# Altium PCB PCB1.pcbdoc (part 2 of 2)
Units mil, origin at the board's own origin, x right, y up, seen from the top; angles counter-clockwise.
Board outline 4205 x 5050 mil, 2 copper layers (Top Layer, Bottom Layer); 96 components, 86 nets, 386 pads, 487 vias.
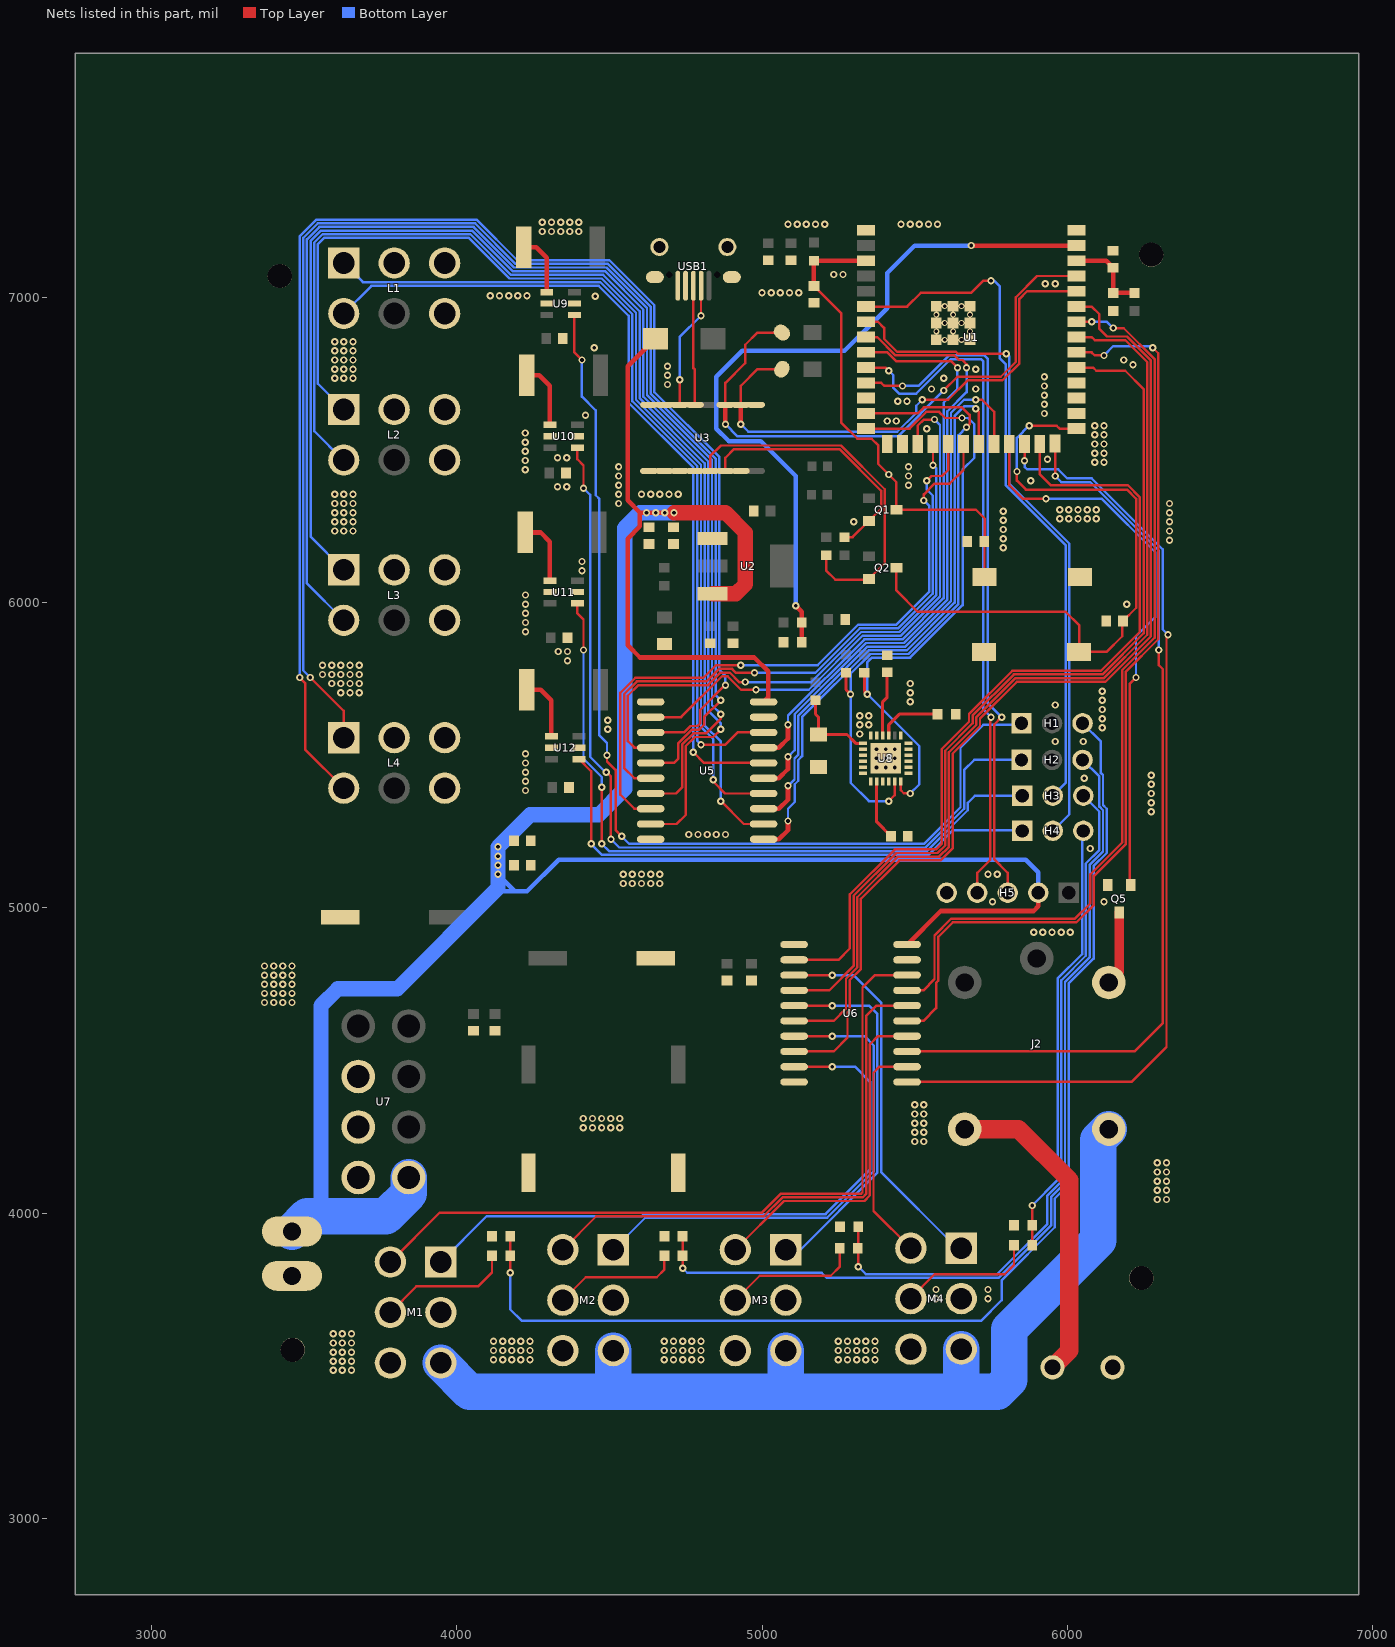
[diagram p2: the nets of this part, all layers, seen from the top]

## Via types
v1: diameter 24.02, hole 12.01, Top Layer to Bottom Layer, 475 vias
v2: diameter 19.69, hole 11.81, Top Layer to Bottom Layer, 12 vias

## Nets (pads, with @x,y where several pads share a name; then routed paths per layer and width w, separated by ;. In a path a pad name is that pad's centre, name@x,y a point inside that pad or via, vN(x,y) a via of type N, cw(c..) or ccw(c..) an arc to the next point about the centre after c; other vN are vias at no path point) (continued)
$1N6809: H3.2 U1.6 | length 2256.7
  Top Layer w8: U1.6@5340.51,6970.19 5475.19,6970.19 5520,7015 5685,7015 5725,7055 v1(5750,7055)
  Bottom Layer w8: v1(5750,7055) 5760,7055 5777.99,7037.01 5777.99,6802.01 5798,6782 5798,6385.03 5994.54,6188.49 5994.54,5409.54 H3.2@5952.5,5367.5
$1N6817: H4.2 U1.7 | length 2195.4
  Top Layer w8: U1.7@5340.51,6920.19 5379.81,6920.19 5400,6900 5400,6864.65 5442.65,6822 5634.97,6822 5641.97,6815 v1(5800,6815)
  Bottom Layer w8: v1(5800,6815) 5801.97,6815 5810,6806.97 5810,6390 6006.54,6193.46 6006.54,5306.54 H4.2@5952.5,5252.5
$2N3281: M1.5 R12.1 | length 441.7
  Top Layer w8: M1.5@3782.33,3675 3867.33,3760 4070,3760 4115.34,3805.34 R12.1@4115.34,3860
$2N3526: M2.5 R14.1 | length 419.2
  Top Layer w8: M2.5@4347.33,3715 4422.33,3790 4655,3790 4680,3815 4680,3859.66 R14.1@4680.34,3860
$2N3663: M3.5 R16.1 | length 449.1
  Top Layer w8: M3.5@4912.33,3715 4992.33,3795 5225,3795 5255,3825 5255,3885.44 R16.1@5254.68,3885.77
$2N3800: M4.5 R18.1 | length 449.7
  Top Layer w8: M4.5@5487.33,3720 5487.33,3722.33 5565,3800 5795,3800 5825.34,3830.34 R18.1@5825.34,3895
$2N3957: J2.4 Q5.3 | length 242.9
  Top Layer w30: J2.4@6136.22,4755.79 6170,4789.57 Q5.3@6170,4984.72
$2N7741: R22.2 U8.9 | length 209.3
  Top Layer w10: U8.9@5414.84,5565.1 5415,5565.26 5415,5600 5449.66,5634.66 R22.2@5575,5634.66
$2N7753: C32.2 U8.10 | length 213.6
  Top Layer w10: U8.10@5395.16,5565.1 5395,5565.26 5395,5675 5410,5690 C32.2@5410,5772.44
$2N7759: C31.2 U8.20 | length 199.4
  Top Layer w10: U8.20@5375.47,5414.9 5375.47,5281.97 C31.2@5422.44,5235
$2N11315: J2.2 P1.1 | length 1048.2
  Top Layer w60: J2.2@5663.81,4275.47 5664.27,4275 5840,4275 6006.55,4108.45 6006.55,3550 P1.1@5951.55,3495
$2N16506: C30.1 R41.1 U8.13 | length 273.2
  Top Layer w10: R41.1@5175,5680.34 5175,5635 5185,5625 C30.1@5185,5568.15 5278.4,5568.15 5307.34,5539.21 U8.13@5329.9,5539.21
+5V: C4.2 C5.2 C28.1 C29.1 D1.1 H5.2 pad.1@3460,3940 U2.3 U5.20 U6.20 U7.4 | length 8374.1
  Top Layer w15: D1.1@4650.51,6865 4560,6774.49 4560,6335 4600,6295 ; v1(4711.58,6295) v1(4681.58,6295) v1(4651.58,6295) v1(4621.58,6295) 4600,6295 ; U5.20@5005.04,5675 5020.04,5690 5020.04,5775 4974.53,5820.51 4600,5820.51 4560,5860.51 4560,6210 4600,6250 4600,6295 ; U6.20@5475.04,4880 5585.04,4990 5890,4990 5905,5005 H5.2@5905,5050
  Top Layer w50: v1(4711.58,6295) 4880,6295 4945,6230 4945,6060.16 4914.29,6029.45 U2.3@4838.07,6029.45
  Bottom Layer w15: 4135,5065 4145,5055 4189.86,5055 ; v1(4135,5109.86) 4189.86,5055 ; H5.2@5905,5050 5905,5116.96 5863.46,5158.5 4333.5,5158.5 4230,5055 4189.86,5055
  Bottom Layer w50: 3555,4040 3555,4680 3610,4735 3805,4735 4135,5065 v1(4135,5109.86) v1(4135,5139.86) v1(4135,5169.86) v1(4135,5200) 4240,5305 4465,5305 4550,5390 4550,6245 4600,6295 v1(4621.58,6295) v1(4651.58,6295) v1(4681.58,6295) v1@4710,6295
  Bottom Layer w120: pad.1@3460,3940 3510,3990 3767.8,3990 3842.68,4064.88 U7.4@3842.68,4116.97
BRAKE: Q5.1 U1.23 | length 1829.9
  Top Layer w8: U1.23@5810,6519.81 5810,6385 5855,6340 v1(5930,6340) ; Q5.1@6207.4,5075.28 6204,5078.68 6204,5734 v1(6225,5755)
  Bottom Layer w8: v1(5930,6340) 6113.03,6340 6288,6165.03 6288,5953 6225,5890 v1(6225,5755)
CHIP_PU: C3.2 C13.2 Q1.3 R2.1 SW1.2 U1.3 | length 1620.3
  Top Layer w8: C3.2@5170,7037.56 5260,6947.56 5260,6589.18 5312.17,6537.01 5359.12,6537.01 5380,6516.12 5380,6455 v1(5415,6420) 5440.28,6394.72 Q1.3@5440.28,6305 5700,6305 5730,6275 5730,6202.44 C13.2@5727.56,6200 5728.66,6198.9 SW1.2@5728.66,6083.65
  Top Layer w15: C3.2@5170,7037.56 R2.1@5170,7120.34 5219.85,7120.34 5220,7120.19 U1.3@5340.51,7120.19
D+: U3.5 USB1.3 | length 392.1
  Top Layer w8: USB1.3@4775,7038.35 4775,6768.35 4780,6763.35 U3.5@4780,6648.35
D-: U3.6 USB1.2 | length 419.2
  Top Layer w8: U3.6@4730,6648.35 v1(4730,6730) ; v1(4800,6940) 4800,7037.86 USB1.2@4800.49,7038.35
  Bottom Layer w8: v1(4730,6730) 4730,6870 v1(4800,6940)
DIR1: U1.25 U6.2 | length 2777.1
  Top Layer w8: U6.2@5104.96,4830 5250,4830 5288,4868 5288,5044.97 5435.03,5192 5570.03,5192 5588,5209.97 5588,5519.97 5678,5609.97 5678,5634.97 5820.03,5777 6110.03,5777 6238,5904.97 6238,6345 6198,6385 5945,6385 5910,6420 U1.25@5910,6519.81
DIR2: U1.31 U6.4 | length 3010.2
  Top Layer w8: U6.4@5104.96,4730 5220,4730 5300,4810 5300,5040 5440,5180 5575,5180 5600,5205 5600,5515 5690,5605 5690,5630 5825,5765 6115,5765 6250,5900 6250,6700 6190,6760 6094.69,6760 6084.49,6770.19 U1.31@6029.49,6770.19
DIR3: U1.33 U6.6 | length 3229
  Top Layer w8: U6.6@5104.96,4630 5235,4630 5275,4670 5275,4768.03 5312,4805.03 5312,5035.03 5444.97,5168 5579.97,5168 5612,5200.03 5612,5510.03 5702,5600.03 5702,5625.03 5829.97,5753 6119.97,5753 6262,5895.03 6262,6788 6190,6860 6089.69,6860 6079.49,6870.19 U1.33@6029.49,6870.19
DIR4: U1.35 U6.8 | length 3418.4
  Top Layer w8: U6.8@5104.96,4530 5235,4530 5280,4575 5280,4658.03 5287,4665.03 5287,4763.06 5324,4800.06 5324,5030.06 5449.94,5156 5584.94,5156 5624,5195.06 5624,5505.06 5714,5595.06 5714,5620.06 5834.94,5741 6124.94,5741 6274,5890.06 6274,6792.97 6194.97,6872 6130,6872 6105,6897 6105,6945 6079.81,6970.19 U1.35@6029.49,6970.19
DTR: Q2.2 R4.1 U3.13 | length 1213.3
  Top Layer w8: U3.13@4830,6431.65 4830,6480 4865,6515 5258.52,6515 5401.91,6371.61 5401.91,6129.78 Q2.2@5349.72,6077.6 5347.13,6075 5240,6075 5210,6105 R4.1@5210,6155.34
ESC1: U1.24 U6.11 | length 3175.7
  Top Layer w8: U6.11@5475.04,4430 6210,4430 6325,4545 6325,5890 v1(6330,5895) ; v1(5860,6465) U1.24@5860,6519.81
  Bottom Layer w8: v1(5860,6465) 5860,6445 5867.99,6437.01 5969.96,6437.01 5999.97,6407 6079.97,6407 6312,6174.97 6312,5913 v1(6330,5895)
ESC2: U1.26 U6.13 | length 2976.3
  Top Layer w8: U6.13@5475.04,4530 6220,4530 6313,4623 6313,5782 6300,5795 v1(6300,5845) ; v1(5960,6415) U1.26@5960,6520.98
  Bottom Layer w8: v1(5960,6415) 5980,6395 6075,6395 6300,6170 v1(6300,5845)
ESC3: U1.32 U6.15 | length 3091
  Top Layer w8: U6.15@5475.04,4630 5528.32,4630 5570,4671.68 5570,4754.71 5577,4761.71 5577,4905.03 5624.97,4953 6029.97,4953 6087,5010.03 6087,5105.03 6192,5210.03 6192,5774.12 6298,5880.12 6298,6817 v1(6280,6835) ; U1.32@6029.49,6820.19 6079.49,6820.19 6089.69,6810 v1(6120,6810)
  Bottom Layer w8: v1(6120,6810) 6150,6840 6275,6840 v1(6280,6835)
ESC4: U1.34 U6.17 | length 2979.5
  Top Layer w8: U6.17@5475.04,4730 5528.32,4730 5565,4766.68 5565,4910 5620,4965 6025,4965 6075,5015 6075,5110 6180,5215 6180,5779.09 6286,5885.09 6286,6797.94 6184.94,6899 6151,6899 v1(6150,6900) ; U1.34@6029.49,6920.19 6029.69,6920 v1(6080,6920)
  Bottom Layer w8: v1(6080,6920) 6130,6920 v1(6150,6900)
FBM1: H1.3 R12.2 R13.1 | length 3959.3
  Top Layer w8: R13.1@4174.66,3925 R12.2@4174.66,3860 4175,3859.66 v1(4175,3805)
  Bottom Layer w8: v1(4175,3805) 4175,3685 4213,3647 5717,3647 5785,3715 5785,3780 5959,3954 5959,4048.09 6004.46,4093.55 6004.46,4752.49 6086,4834.03 6086,5137.06 6129,5180.06 6129,5324.94 6117,5336.94 6117,5434.97 6110,5441.97 6110,5545 H1.3@6050,5605
FBM2: H2.3 R14.2 R15.1 | length 3019.8
  Top Layer w8: R15.1@4739.66,3925 R14.2@4739.66,3860 4740,3859.66 v1(4740,3820)
  Bottom Layer w8: v1(4740,3820) 4755,3805 5195,3805 5212,3788 5774.97,3788 5947,3960.03 5947,4053.06 5992.46,4098.52 5992.46,4757.46 6074,4839 6074,5142.03 6117,5185.03 6117,5319.97 6105,5331.97 6105,5430 H2.3@6050,5485
FBM3: H3.3 R16.2 R17.1 | length 2324.1
  Top Layer w8: R17.1@5314.66,3955 5314.66,3886.43 R16.2@5313.99,3885.77 5315,3884.76 v1(5315,3825)
  Bottom Layer w8: v1(5315,3825) 5340,3800 5770,3800 5935,3965 5935,4058.03 5980.46,4103.49 5980.46,4763.3 6060.46,4843.3 6060.46,5145.46 6105,5190 6105,5315 H3.3@6052.5,5367.5
FBM4: H4.3 R18.2 R19.1 | length 1427
  Top Layer w8: R18.2@5884.66,3895 R19.1@5884.66,3960 5885,3960.34 v1(5885,4025)
  Bottom Layer w8: v1(5885,4025) 5968.46,4108.46 5968.46,4768.27 6048.46,4848.27 6048.46,5248.46 H4.3@6052.5,5252.5
GND: C1.1 C2.1 C3.1 C4.1 C5.1 C6.1 C7.1 C12.2 C13.1 C14.1 C15.2 C20.2 C21.2 C22.2 C23.2 C24.2 C25.2 C26.2 C27.2 C28.2 C29.2 C30.2 C31.1 C32.1 C33.2 C34.2 C35.2 C36.2 C37.2 H5.5 L1.3 L1.6 L2.3 L2.6 L3.3 L3.6 L4.3 L4.6 LED5.1 M1.6 M2.6 M3.6 M4.6 P1.2 pad.1@3460,3795 Q5.2 R9.1 R11.2 R13.2 R15.2 R17.2 R19.2 R22.1 SW1.1 SW2.1 U1.1 U1.40 U1.41 U2.1 U3.1 U5.1 U5.10 U5.19 U6.1 U6.10 U6.19 U7.5 U7.6 U7.7 U8.1 U8.11 U8.18 U8.25 U9.2 U9.5 U10.2 U10.5 U11.2 U11.5 U12.2 U12.5 USB1.5
  other v1: 3595,3485 3625,3485 3655,3485 3595,3515 3625,3515 3655,3515 4120,3520 4150,3520 4180,3520 4210,3520 4240,3520 4680,3520 4710,3520 4740,3520 4770,3520 4800,3520 5250,3520 5280,3520 5310,3520 5340,3520 5370,3520 3595,3545 3625,3545 3655,3545 4120,3550 4150,3550 4180,3550 4210,3550 4240,3550 4680,3550 4710,3550 4740,3550 4770,3550 4800,3550 5250,3550 5280,3550 5310,3550 5340,3550 5370,3550 3595,3575 3625,3575 3655,3575 4120,3580 4150,3580 4180,3580 4210,3580 4240,3580 4680,3580 4710,3580 4740,3580 4770,3580 4800,3580 5250,3580 5280,3580 5310,3580 5340,3580 5370,3580 3595,3605 3625,3605 3655,3605 5570,3720 5740,3720 5570,3750 5740,3750 6295,4045 6325,4045 6295,4075 6325,4075 6295,4105 6325,4105 6295,4135 6325,4135 6295,4165 6325,4165 5500,4235 5530,4235 5500,4265 5530,4265 4414.31,4280.01 4444.31,4280.01 4474.31,4280.01 4504.31,4280.01 4534.31,4280.01 5500,4295 5530,4295 4414.31,4310.01 4444.31,4310.01 4474.31,4310.01 4504.31,4310.01 4534.31,4310.01 5500,4325 5530,4325 5500,4355 5530,4355 3370,4690 3400,4690 3429.45,4690 3460,4690 3370,4720 3400,4720 3429.45,4720 3460,4720 3370,4750 3400,4750 3429.45,4750 3460,4750 3370,4780 3400,4780 3429.45,4780 3460,4780 3370,4810 3400,4810 3429.45,4810 3460,4810 5890,4920 5920,4920 5950,4920 5980,4920 6010,4920 5755,5020 6120,5020 4545,5080 4575,5080 4605,5080 4635,5080 4665,5080 5740,5110 5770,5110 6075,5195 4760,5240.64 4790,5240.64 4820,5240.64 4850,5240.64 4880,5240.64 6275,5315 6275,5345 6275,5375 4225,5385 6275,5405 4225,5415 6055,5425 6275,5435 4225,5445 5375,5460 5405,5460 5435,5460 4225,5475 5375,5490 5405,5490 5435,5490 4225,5505 5375,5520 5405,5520 5435,5520 5960,5545 6052.11,5545 5320,5570 4495,5585 6115,5590 5320,5600 5350,5600 4495,5615 6115,5620 5320,5630 5350,5630 6115,5650 5960,5665 5485,5675 6115,5680 3620,5705 3650,5705 3680,5705 5485,5705 6115,5710 3590,5735 3620,5735 3650,5735 3680,5735 5485,5735 3560,5765 3590,5765 3620,5765 3650,5765 3680,5765 3560,5795 3590,5795 3620,5795 3650,5795 3680,5795 4362.56,5809.95 4332.56,5839.95 4362.56,5839.95 4225,5905 4225,5935 4225,5965 4225,5995 6195,5995 4225,6025 4410,6105 4410,6135 4410,6135 5790,6180 6335,6205 5790,6210 3600,6235 3630,6235 3660,6235 6335,6235 5790,6240 3600,6265 3630,6265 3660,6265 5300,6265 6335,6265 5790,6270 5975,6275 6005,6275 6035,6275 6065,6275 6095,6275 3600,6295 3630,6295 3660,6295 6335,6295 5790,6300 5975,6305 6005,6305 6035,6305 6065,6305 6095,6305 3600,6325 3630,6325 3660,6325 4530,6325 6335,6325 3600,6355 3630,6355 3660,6355 4530,6355 4605,6355 4635,6355 4665,6355 4695,6355 4725,6355 4330,6380 4360,6380 4530,6385 5480,6385 5880,6400 4530,6415 5480,6415 4224.28,6435.84 4530,6445 5480,6445 6090,6460 6120,6460 4224.28,6465.84 5935,6470 4330,6475 4360,6475 6090,6490 6120,6490 4224.28,6495.84 6090,6520 6120,6520 4224.28,6525.84 6090,6550 6120,6550 4224.28,6555.84 5540,6570 6090,6580 6120,6580 5410,6595 5439.29,6595.23 4421.65,6614.19 5925,6620 5925,6650 5445,6660 5475,6660 5925,6680 5555,6700 5700,6700 5925,6710 4690,6715 3600,6735 3630,6735 3660,6735 5595,6735 5925,6740 4690,6745 3600,6765 3630,6765 3660,6765 5700,6765 4690,6775 6215,6780 3600,6795 3630,6795 3660,6795 6185,6795 3600,6825 3630,6825 3660,6825 4450,6835 3600,6855 3630,6855 3660,6855 4453.98,7004.39 4110,7005 4140,7005 4170,7005 4200,7005 4230,7005 5000,7015 5030,7015 5060,7015 5090,7015 5120,7015 5927.47,7045 5960,7045 5235,7075 5265,7075 4280,7215.92 4310,7215.92 4340,7215.92 4370,7215.92 4400,7215.92 5085,7240 5115,7240 5145,7240 5175,7240 5205,7240 5455,7240 5485,7240 5515,7240 5545,7240 5575,7240 4280,7245.92 4310,7245.92 4340,7245.92 4370,7245.92 4400,7245.92
GPIO0: C14.2 Q2.3 SW2.2 U1.27 | length 2201.2
  Top Layer w8: Q2.3@5440.28,6115 5440,6114.72 5440,6040 5510,5970 5995,5970 6038.65,5926.35 SW2.2@6038.65,5838.66 6128.66,5838.66 6180,5890 6180,5937.44 C14.2@6182.56,5940 6226,5983.44 6226,6340.03 6195.51,6370.51 5864.49,6370.51 5835,6400 v1@5835,6420 ; v1(5875,6580) 5875.67,6579.33 5965.35,6579.33 5974.49,6570.19 U1.27@6029.49,6570.19
  Bottom Layer w8: v1(5835,6430) 5835,6540 v1(5875,6580)
H1: U1.17 U5.2 | length 1859.1
  Top Layer w8: U5.2@4634.96,5625 4735,5625 4869,5759 4887.12,5759 4931.12,5715 v1(4980,5715) ; U1.17@5510,6519.81 5510,6580 5530,6600 v1(5565,6600)
  Bottom Layer w8: v1(4980,5715) 5153.03,5715 5330.03,5892 5455.03,5892 5583,6019.97 5583,6582 v1(5565,6600)
H1CS: H1.1 U9.1 | length 3370.1
  Top Layer w8: U9.1@4385.24,6942.6 4385.24,6820 v1(4410,6795.24) v1@4410,6795 ; v1(4492,5500) 4492,5480 4520,5452 4520,5255 v1(4540,5235)
  Bottom Layer w8: v1(4410,6795.24) 4410,6675 4455,6630 4455,6351.97 4467,6339.97 4467,5564.97 4492,5539.97 v1(4492,5500) ; v1(4540,5235) 4565,5210 5530,5210 5650,5330 5650,5525 5725,5600 5845,5600 H1.1@5850,5605
H2: U1.19 U5.6 | length 2047.9
  Top Layer w8: U5.6@4634.96,5425 4581.68,5425 4548,5458.68 4548,5699.97 4590.03,5742 4818.06,5742 4859.06,5783 4902,5783 4915,5770 v1(4975,5770) ; v1(5540,6400) 5555,6415 5590,6415 5610,6435 U1.19@5610,6519.81
  Bottom Layer w8: v1(4975,5770) 5174.09,5770 5320.09,5916 5445.03,5916 5559,6029.97 5559,6351 5540,6370 v1(5540,6400)
H2CS: H2.1 U10.1 | length 2879.3
  Top Layer w8: U10.1@4395.24,6507.6 4395.24,6469.76 4415,6450 v1(4415,6375) ; v1(4490,5445) 4505,5430 v1(4505,5225)
  Bottom Layer w8: v1(4415,6375) 4437.01,6352.99 4437.01,5494.96 4482.66,5449.31 4485.69,5449.31 v1(4490,5445) ; v1(4505,5225) 4532,5198 5534.97,5198 5662,5325.03 5662,5452 5695,5485 H2.1@5850,5485
H3: U1.21 U5.11 | length 1953.5
  Top Layer w8: v1(5700,6635) 5710,6625 U1.21@5710,6519.81
  Top Layer w15: U5.11@5005.04,5225 5055,5225 5085,5255 v1(5085,5285)
  Bottom Layer w8: v1(5085,5285) 5085,5325 5107.01,5347.01 5107.01,5405.04 5118.47,5416.5 5118.47,5484.63 5131.01,5497.17 5131.01,5625.1 5349.91,5844 5474.91,5844 5631,6000.09 5631,6612.06 5662.17,6643.23 5691.77,6643.23 v1(5700,6635)
H3CS: H3.1 U11.1 | length 2297.3
  Top Layer w8: U11.1@4395.24,5997.6 4395.24,5964.76 4415,5945 v1(4415,5845) ; v1(4475,5210) v1(4475,5395)
  Bottom Layer w8: v1(4415,5845) 4415,5488.88 4475,5428.88 v1(4475,5395) ; v1(4475,5210) 4499,5186 5539.94,5186 5674,5320.06 5674,5344 5697.5,5367.5 H3.1@5852.5,5367.5
H4: U1.8 U5.15 | length 2100.5
  Top Layer w8: U1.8@5340.51,6870.19 5377.48,6870.19 5437.68,6810 5630,6810 5645,6795 5656.31,6795 5670,6781.31 v1(5670,6770)
  Top Layer w15: U5.15@5005.04,5425 5055,5425 5085,5455 v1(5085,5495)
  Bottom Layer w8: v1(5085,5495) 5107.01,5517.01 5107.01,5635.04 5339.97,5868 5464.97,5868 5607,6010.03 5607,6627 5670,6690 v1(5670,6770)
H4CS: H4.1 U12.1 | length 1756.1
  Top Layer w8: U12.1@4400.24,5487.6 4440,5447.84 v1(4440,5210)
  Bottom Layer w8: v1(4440,5210) 4476,5174 5544.91,5174 5625.91,5255 5850,5255 H4.1@5852.5,5252.5
HAM1: L1.1 U5.18 | length 2739.6
  Top Layer w8: v1(4800,5535) 4880,5535 4920,5575 U5.18@5005.04,5575
  Bottom Layer w8: L1.1@3629.64,7112.68 3692.33,7050 4470,7050 4575,6945 4575,6660 4788,6447 4788,5547 v1(4800,5535)
HAM2: L2.1 U5.14 | length 3551
  Top Layer w8: v1(4840,5420) 4840,5414.18 4879.18,5375 U5.14@5005.04,5375
  Bottom Layer w8: L2.1@3629.64,6632.68 3545,6717.33 3545,7175 3565,7195 4040,7195 4173,7062 4474.97,7062 4587,6949.97 4587,6664.97 4800,6451.97 4800,5593.03 4840,5553.03 v1(4840,5420)
HAM3: L3.1 U5.9 | length 4304.1
  Top Layer w8: U5.9@4634.96,5275 4720,5275 4750,5305 4750,5530 4780,5560 4840,5560 v1(4865,5585)
  Bottom Layer w8: L3.1@3629.64,6107.68 3521,6216.33 3521,7184.94 3555.06,7219 4049.94,7219 4182.94,7086 4484.91,7086 4611,6959.91 4611,6674.91 4824,6461.91 4824,5644.88 4865,5603.88 v1(4865,5585)
HAM4: L4.1 U5.5 | length 4707.2
  Top Layer w8: v1(3520,5755) 3629.65,5645.35 L4.1@3629.64,5557.68 ; U5.5@4634.96,5475 4711,5475 4726,5490 4726,5539.94 4770.06,5584 4794,5584 4810,5600 4810,5625 v1(4865,5680)
  Bottom Layer w8: v1(3520,5755) 3497,5778 3497,7194.88 3545.12,7243 4059.88,7243 4192.88,7110 4494.85,7110 4635,6969.85 4635,6684.85 4848,6471.85 4848,5697 v1(4865,5680)
IN-1: L1.2 R37.1 U9.4 | length 202.7
  Top Layer w15: R37.1@4219.28,7165 4260,7165 4294.76,7130.24 U9.4@4294.76,7017.4
IN-2: L2.2 R38.1 U10.4 | length 217.7
  Top Layer w15: R38.1@4229.28,6745 4270,6745 4304.76,6710.24 U10.4@4304.76,6582.4
IN-3: L3.2 R39.1 U11.4 | length 220.7
  Top Layer w15: R39.1@4224.28,6230 4275,6230 4304.76,6200.24 U11.4@4304.76,6072.4
IN-4: L4.2 R40.1 U12.4 | length 212.7
  Top Layer w15: R40.1@4229.28,5715 4275,5715 4309.76,5680.24 U12.4@4309.76,5562.4
M+: J2.3 M1.3 M2.3 M3.3 M4.3 | length 3288.9
  Bottom Layer w120: M1.3@3947.67,3509.65 4042.32,3415 4507.7,3415 ; M2.3@4512.67,3549.65 4512.67,3419.97 4507.7,3415 ; M3.3@5077.67,3549.65 5077.67,3416.45 5076.22,3415 ; M4.3@5652.67,3554.65 5652.67,3423.73 5643.94,3415 ; J2.3@6136.2,4275.47 6101.2,4240.47 6101.2,3911.2 5810,3620 5810,3455 5770,3415 5643.94,3415 ; 4507.7,3415 5076.22,3415 ; 5076.22,3415 5643.94,3415
MDIR1: M1.4 U6.18 | length 2475
  Top Layer w8: M1.4@3782.33,3840.35 3943.98,4002 5000.04,4002 5062.04,4064 5325.06,4064 5329,4067.94 5329,4739 5370,4780 U6.18@5475.04,4780
MDIR2: M2.4 U6.16 | length 1800.5
  Top Layer w8: M2.4@4347.33,3880.35 4456.98,3990 5005.01,3990 5067.01,4052 5330.03,4052 5341,4062.97 5341,4646 5375,4680 U6.16@5475.04,4680
MDIR3: M3.4 U6.14 | length 1142.5
  Top Layer w8: M3.4@4912.33,3880.35 5071.98,4040 5335,4040 5353,4058 5353,4553 5380,4580 U6.14@5475.04,4580
MDIR4: M4.4 U6.12 | length 743.6
  Top Layer w8: U6.12@5475.04,4480 5385,4480 5365,4460 5365,4007.68 M4.4@5487.33,3885.35
MESC1: M1.1 U6.9 | length 2088.5
  Top Layer w8: U6.9@5104.96,4480 v1(5230,4480)
  Bottom Layer w8: M1.1@3947.67,3840.35 4097.33,3990 4605.36,3990 4612.36,3997 5208.06,3997 5354,4142.94 5354,4430 5304,4480 v1(5230,4480)
MESC2: M2.1 U6.7 | length 1644.9
  Top Layer w8: U6.7@5104.96,4580 v1(5230,4580)
  Bottom Layer w8: M2.1@4512.67,3880.35 4617.33,3985 5213.03,3985 5366,4137.97 5366,4549 5335,4580 v1(5230,4580)
MESC3: M3.1 U6.5 | length 1208.6
  Top Layer w8: U6.5@5104.96,4680 v1(5230,4680)
  Bottom Layer w8: M3.1@5077.67,3880.35 5125.35,3880.35 5378,4133 5378,4652 5350,4680 v1(5230,4680)
MESC4: M4.1 U6.3 | length 1243.4
  Top Layer w8: U6.3@5104.96,4780 v1(5230,4780)
  Bottom Layer w8: v1(5230,4780) 5300,4780 5390,4690 5390,4135 5639.65,3885.35 M4.1@5652.67,3885.35
RTS: Q1.2 R5.1 U3.14 | length 838.7
  Top Layer w8: U3.14@4880,6431.65 4880,6475 4908,6503 5253.55,6503 5389.91,6366.64 5389.91,6307.78 Q1.2@5349.72,6267.6 5296.79,6214.66 R5.1@5270,6214.66
RXD0: LED4.2 U1.36 U3.2 | length 1720.5
  Top Layer w8: U3.2@4930,6648.35 4930,6710 4985,6765 LED4.2@5065,6765 ; v1(5525,6665) 5610,6665 5673,6728 5786.97,6728 5843,6784.03 5843,6995.22 5867.97,7020.19 U1.36@6029.49,7020.19
  Top Layer w15: v1(4930,6585) U3.2@4930,6648.35
  Bottom Layer w8: v1(4930,6585) 4955,6560 5443.03,6560 5505,6621.97 5505,6645 v1(5525,6665)
RXD1: H5.3 U1.11 | length 2246.3
  Top Layer w8: U1.11@5340.51,6720.19 5390.51,6720.19 5400.7,6710 v1(5460,6710) ; v1(5785,5625) 5760,5600 5760,5160 5805,5115 H5.3@5805,5050
  Bottom Layer w8: v1(5460,6710) 5513.03,6710 5613.03,6810 5729,6810 5739,6800 5739,5671 v1(5785,5625)
S1: U1.18 U5.4 | length 1905
  Top Layer w8: U5.4@4634.96,5525 4581.68,5525 4560,5546.68 4560,5695 4595,5730 4823.03,5730 4864.03,5771 4894,5771 4925,5740 v1(4945,5740) ; v1(5560,6450) U1.18@5560,6519.81
  Bottom Layer w8: v1(4945,5740) 5161.06,5740 5325.06,5904 5450,5904 5571,6025 5571,6439 v1(5560,6450)
S2: U1.20 U5.8 | length 2174.9
  Top Layer w8: U5.8@4634.96,5325 4581.68,5325 4536,5370.68 4536,5704.94 4585.06,5754 4808.09,5754 4849.09,5795 v1(4930,5795) ; v1(5530,6335) 5530,6355 5565,6390 5615,6390 5660,6435 U1.20@5660,6519.81
  Bottom Layer w8: v1(4930,5795) 5182.12,5795 5315.12,5928 5440.06,5928 5547,6034.94 5547,6318 v1(5530,6335)
S3: U1.22 U5.13 | length 1934.8
  Top Layer w8: v1(5700,6665) 5720.63,6665 5760,6625.63 U1.22@5760,6519.81
  Top Layer w15: U5.13@5005.04,5325 5055,5325 5085,5355 v1(5085,5400)
  Bottom Layer w8: v1(5085,5400) 5106.29,5421.29 5106.29,5489.42 5119.01,5502.14 5119.01,5630.07 5344.94,5856 5469.94,5856 5619,6005.06 5619,6622.03 5661.97,6665 v1(5700,6665)
S4: U1.9 U5.17 | length 1930.8
  Top Layer w8: U1.9@5340.51,6820.19 5410.51,6820.19 5439.29,6791.41 5618.59,6791.41 v1(5640,6770)
  Top Layer w15: U5.17@5005.04,5525 5055,5525 5085,5555 v1(5085,5600)
  Bottom Layer w8: v1(5085,5600) 5085,5630 5335,5880 5460,5880 5595,6015 5595,6655 5640,6700 v1(5640,6770)
SCL0: R20.1 U1.13 U8.23 | length 2097.2
  Top Layer w8: U1.13@5340.51,6620.19 5510.19,6620.19 5530,6640 5655,6640 5680,6615 5680,6585 v1(5670,6575) ; v1(5415,5350) 5434.53,5369.53 U8.23@5434.53,5414.9
  Top Layer w10: R20.1@5275,5770.34 5275,5715 v1(5290,5700)
  Bottom Layer w8: v1(5415,5350) 5350,5350 5290,5410 v1(5290,5700) 5290,5767.12 5354.88,5832 5479.88,5832 5643,5995.12 5643,6548 v1(5670,6575)
SDA0: R21.1 U1.14 U8.24 | length 2043.7
  Top Layer w8: U1.14@5340.51,6570.19 5483.22,6570.19 5538.03,6625 5580,6625 5600,6605 v1(5655,6605) ; U8.24@5454.21,5414.9 5454.21,5385.79 5464.21,5375.79 5484.21,5375.79 v1(5485,5375)
  Top Layer w10: R21.1@5335,5770.34 5335,5710 v1(5345,5700)
  Bottom Layer w8: v1(5485,5375) 5515,5405 5515,5530 v1(5345,5700) 5345,5805.15 5359.85,5820 5484.85,5820 5657,5992.15 5657,6435.99 5695,6473.99 5695,6585 5675,6605 v1(5655,6605)
SH1: L1.4 U5.16 | length 2773.9
  Top Layer w8: v1(4775,5510) 4810,5475 U5.16@5005.04,5475
  Bottom Layer w8: L1.4@3629.64,6947.33 3720.32,7038 4465.03,7038 4563,6940.03 4563,6655.03 4775,6443.03 v1(4775,5510)
SH2: L2.4 U5.12 | length 3821.7
  Top Layer w8: v1(4865,5350) 4940,5275 U5.12@5005.04,5275
  Bottom Layer w8: L2.4@3629.64,6467.33 3627.67,6467.33 3533,6562 3533,7179.97 3560.03,7207 4044.97,7207 4177.97,7074 4479.94,7074 4599,6954.94 4599,6669.94 4812,6456.94 4812,5598 4865,5545 v1(4865,5350)
SH3: L3.4 U5.7 | length 4396.8
  Top Layer w8: U5.7@4634.96,5375 4718,5375 4738,5395 4738,5534.97 4775.03,5572 4815.88,5572 4865,5621.12 v1(4865,5635)
  Bottom Layer w8: L3.4@3629.64,5942.33 3509,6062.98 3509,7189.91 3550.09,7231 4054.91,7231 4187.91,7098 4489.88,7098 4623,6964.88 4623,6679.88 4836,6466.88 4836,5664 v1(4865,5635)
SH4: L4.4 U5.3 | length 4844.9
  Top Layer w8: v1(3485,5755) 3503,5737 3503,5518.98 L4.4@3629.64,5392.33 ; U5.3@4634.96,5575 4744.09,5575 4765.09,5596 4789.03,5596 4798,5604.97 4798,5649.31 4878.69,5730 v1(4880,5730)
  Bottom Layer w8: v1(3485,5755) 3485,7199.85 3540.15,7255 4064.85,7255 4197.85,7122 4499.82,7122 4647,6974.82 4647,6689.82 4860,6476.82 4860,5780 4880,5760 v1(4880,5730)
TEMP: R8.1 R9.2 U1.39 | length 2472.4
  Top Layer w15: v1(5110,5990) 5129.66,5970.34 R8.1@5129.66,5935 R9.2@5129.66,5870 ; v1(5685,7170) 6029.3,7170 U1.39@6029.49,7170.19
  Bottom Layer w15: v1(5110,5990) 5110,6415 4995.5,6529.5 4890.5,6529.5 4850,6570 4850,6740 4935,6825 5270,6825 5410,6965 5410,7080 5500,7170 v1(5685,7170)
TXD0: LED3.2 U1.37 U3.3 | length 1930.8
  Top Layer w8: U3.3@4880,6648.35 4880,6720 4945,6785 4945,6845 4985,6885 LED3.2@5065,6885 ; v1(5595,6695) 5640,6740 5782,6740 5831,6789 5831,7000.19 5901,7070.19 U1.37@6029.49,7070.19
  Top Layer w15: v1(4880,6585) U3.3@4880,6648.35
  Bottom Layer w8: v1(4880,6585) 4920,6545 5445,6545 v1(5595,6695)
TXD1: H5.4 U1.10 | length 2263
  Top Layer w8: U1.10@5340.51,6770.19 5404.81,6770.19 v1(5415,6760) ; H5.4@5705,5050 5705,5115 5748,5158 5748,5623 v1(5750,5625)
  Bottom Layer w8: v1(5415,6760) 5430,6745 5430,6703.88 5448.88,6685 5505,6685 5618,6798 5717,6798 5725,6790 5725,5650 v1(5750,5625)
VBATT: C15.1 R10.2 R11.1 U1.38 | length 282.7
  Top Layer w15: U1.38@6029.49,7120.19 6127.24,7120.19 C15.1@6150,7097.44 R11.1@6150,7014.66 R10.2@6220,7014.66
"": M1.2 M2.2 M3.2 M4.2 SCREW3.1 SCREW4.1 U1.12 U1.15 U1.16 U1.28 U1.29 U1.30 U3.7 U3.8 U3.9 U3.10 U3.11 U3.12 U3.15 U8.2 U8.3 U8.4 U8.5 U8.6 U8.7 U8.12 U8.14 U8.15 U8.16 U8.17 U8.19 U8.21 U8.22 USB1.0 USB1.4 USB1.6 USB1.7 USB1.8 USB1.9 USB1.10
  other v1: 4545,5110 4575,5110 4605,5110 4635,5110 4665,5110
  other v2: 5598.38,6861.14 5653.5,6861.14 5570.82,6888.7 5625.94,6888.7 5681.06,6888.7 5598.38,6916.26 5653.5,6916.26 5570.82,6943.81 5625.94,6943.81 5681.06,6943.81 5598.38,6971.37 5653.5,6971.37

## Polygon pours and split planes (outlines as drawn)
GND on Bottom Layer (solid, remove dead copper, pour order 0): 3000,3000 6705,3000 6705,7550 3000,7550
12.6VDC on Top Layer (solid, remove dead copper, pour order 1): 4845,4800 5005,4800 5005,4965 4845,4965
7.4VDC on Top Layer (solid, remove dead copper, pour order 2): 4170,4400 4795,4400 4795,4585 4170,4585
+5V on Top Layer (solid, remove dead copper, pour order 3): 4100,5095 4215,5095 4215,5260 4100,5260
+5V on Top Layer (solid, remove dead copper, pour order 4): 4575,6225 4760,6225 4760,6320 4575,6320
GND on Top Layer (solid, remove dead copper, pour order 9): 3135,3130 6475,3130 6475,7480 3135,7480
IN-3 on Top Layer (solid, remove dead copper, pour order 5): 4250,6310 3710,6305 3711.27,6030 3880,6030 3880,6190 4064.59,6190 4105,6149.59 4250,6149.59
IN-2 on Top Layer (solid, remove dead copper, pour order 6): 4255,6825 3715,6825 3715.63,6542.5 3884.37,6542.5 3884.37,6702.5 4068.96,6702.5 4109.37,6662.09 4254.37,6662.09
IN-4 on Top Layer (solid, remove dead copper, pour order 7): 4255,5795 3715,5795 3715.63,5490 3885,5490 3884.37,5672.5 4068.96,5672.5 4109.37,5632.09 4254.37,5632.09
IN-1 on Top Layer (solid, remove dead copper, pour order 8): 3715,7030 3715,7272.01 4246.47,7272.01 4246.47,7087.97 4185.03,7087.97 4120.62,7087.97 4039.41,7180 3870,7180 3870,7030

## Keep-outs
Board Outline Layer:
  lines w10 net "": 3340,3500 3340,7107.01 3505,7272.01 6260.91,7272.01 6360,7172.91 6360,3434.09 6260.91,3335 3505,3335 3340,3500

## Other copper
Top Layer:
  drawing of 339 lines, arcs and shapes, not listed
Bottom Layer:
  drawing of 122 lines, arcs and shapes, not listed

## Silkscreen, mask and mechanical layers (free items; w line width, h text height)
Top Silkscreen Layer:
  text "V1.0" at 5355.25,4927.54 h67.97
  text "TO Rpi4B PW" at 3362.54,4378.57 h67.97 r270
  text "designed by  /  MackaJunest" at 5038.44,4135.54 h90.26
  text "+5V" at 3430.08,3997.54 h67.97
  text "GND" at 3380.08,3677.54 h67.97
